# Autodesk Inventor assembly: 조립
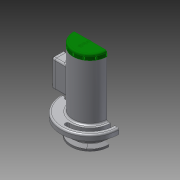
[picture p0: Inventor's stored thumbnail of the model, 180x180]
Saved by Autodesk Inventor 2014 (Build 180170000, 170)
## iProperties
Created: 2017-05
Part Number: 조립
Document SubType Name: Assembly
Designer: Administrator
Author: Administrator
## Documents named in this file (20)
- C:\Users\Administrator\Desktop\새 폴더\470508V1009\조립.iam
- C:\Users\Administrator\Desktop\새 폴더\470508V1009\1-본체.ipt
- C:\Users\Administrator\Desktop\새 폴더\470508V1009\V-벨트풀리.ipt
- C:\Users\Administrator\Desktop\새 폴더\470508V1009\너트 M10.ipt
- C:\Users\Administrator\Desktop\새 폴더\470508V1009\멈춤링 15 x 1.ipt
- C:\Users\Administrator\Desktop\새 폴더\470508V1009\멈춤링 35x1.6.ipt
- C:\Users\Administrator\Desktop\새 폴더\470508V1009\베어링 15 x 35 x 11.ipt
- C:\Users\Administrator\Desktop\새 폴더\470508V1009\볼트 M4 x 10.ipt
- C:\Users\Administrator\Desktop\새 폴더\470508V1009\부시1.ipt
- C:\Users\Administrator\Desktop\새 폴더\470508V1009\부시2.ipt
- C:\Users\Administrator\Desktop\새 폴더\470508V1009\사이드 커버.ipt
- 사이드 커버.ipt
- C:\Users\Administrator\Desktop\새 폴더\470508V1009\십자볼트 M3 x 10.ipt
- C:\Users\Administrator\Desktop\새 폴더\470508V1009\오일 실 15 25 7.ipt
- C:\Users\Administrator\Desktop\새 폴더\470508V1009\와셔 3x6.ipt
- C:\Users\Administrator\Desktop\새 폴더\470508V1009\와셔 4x16.ipt
- C:\Users\Administrator\Desktop\새 폴더\470508V1009\와셔 10x21.ipt
- C:\Users\Administrator\Desktop\새 폴더\470508V1009\축.ipt
- C:\Users\Administrator\Desktop\새 폴더\470508V1009\키 4 x 4 x 18.ipt
- C:\Users\Administrator\Desktop\새 폴더\470508V1009\탑 커버.ipt
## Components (3 placed, 3 different names)
1. 1-본체:1 — Mate:1, Mate:2, Mate:3, Mate:4, Mate:5, Mate:6, Mate:7, Mate:8, Mate:9, Mate:11, Mate:12, Mate:14, Mate:25, Mate:26, Mate:27
2. V-벨트풀리:1 — Mate:18, Mate:19, Mate:20
3. ISO 4017 M4 x 10:1 — Mate:21, Mate:24
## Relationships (20: Mate 20)
- Mate:1: 1-본체:1
- Mate:2: 1-본체:1
- Mate:3: 1-본체:1
- Mate:4: 1-본체:1
- Mate:5: 1-본체:1
- Mate:6: 1-본체:1
- Mate:7: 1-본체:1
- Mate:8: 1-본체:1
- Mate:9: 1-본체:1
- Mate:11: 1-본체:1
- Mate:12: 1-본체:1
- Mate:14: 1-본체:1
- Mate:18: V-벨트풀리:1
- Mate:19: V-벨트풀리:1
- Mate:20: V-벨트풀리:1
- Mate:21: ISO 4017 M4 x 10:1
- Mate:24: ISO 4017 M4 x 10:1
- Mate:25: 1-본체:1
- Mate:26: 1-본체:1
- Mate:27: 1-본체:1
